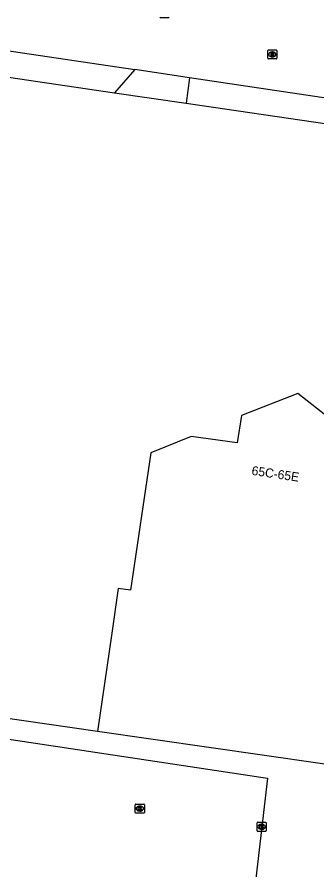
# Model space of a CAD drawing. Extents: x 163686 to 164493, y 382719 to 383870.
# Drawn here: x 163872 to 163905.1, y 382846.6 to 382940.9 of the extents above; entities that cross this region are included whole.
import ezdxf

# ---------------------------------------------------------------- set-up
doc = ezdxf.new("R2010")
doc.units = 0
for name, color, linetype in [('IMGEO_Groenvoorziening', 7, 'Continuous'), ('IMGEO_Hek', 7, 'Continuous'), ('IMGEO_Kolk', 7, 'Continuous'), ('IMGEO_Pand', 7, 'Continuous'), ('IMGEO_Pand_nummerreeks', 7, 'Continuous'), ('IMGEO_Parkeervlak_open', 7, 'Continuous'), ('IMGEO_Rijbaan_lokaal_gesloten', 7, 'Continuous'), ('IMGEO_Rioolput', 7, 'Continuous'), ('IMGEO_Voetpad_open', 7, 'Continuous')]:
    doc.layers.add(name, color=color, linetype=linetype)

msp = doc.modelspace()

# ---------------------------------------------------------------- linework, layer by layer
at = {"layer": 'IMGEO_Groenvoorziening'}
msp.add_lwpolyline([(163880.827, 382861.884), (163850.77, 382866.239), (163850.464, 382866.285)], dxfattribs=at)
at = {"layer": 'IMGEO_Hek'}
msp.add_lwpolyline([(163880.827, 382861.884), (163850.77, 382866.239), (163850.464, 382866.285)], dxfattribs=at)
at = {"layer": 'IMGEO_Kolk'}
for p, q in [((163888.672, 382940.839), (163887.82, 382940.839)), ((163885.017, 382852.936), (163885.017, 382853.788)), ((163885.092, 382853.862), (163885.944, 382853.862)), ((163885.505, 382853.642), (163885.53, 382853.642)), ((163886.018, 382853.788), (163886.018, 382852.936)), ((163885.944, 382852.862), (163885.092, 382852.862)), ((163885.528, 382853.082), (163885.503, 382853.082)), ((163898.468, 382850.916), (163898.468, 382851.768)), ((163898.543, 382851.842), (163899.395, 382851.842)), ((163898.956, 382851.622), (163898.981, 382851.622)), ((163899.469, 382851.768), (163899.469, 382850.916)), ((163899.395, 382850.842), (163898.543, 382850.842)), ((163898.979, 382851.062), (163898.954, 382851.062))]:
    msp.add_line(p, q, dxfattribs=at)
for points in [[(163888.672, 382940.839), (163887.82, 382940.839)], [(163885.017, 382852.936), (163885.017, 382853.788)], [(163885.092, 382853.862), (163885.944, 382853.862)], [(163885.338, 382853.562), (163885.461, 382853.562), (163885.461, 382853.411), (163885.591, 382853.562), (163885.755, 382853.562), (163885.609, 382853.411), (163885.762, 382853.162), (163885.61, 382853.162), (163885.525, 382853.326), (163885.461, 382853.259), (163885.461, 382853.162), (163885.338, 382853.162), (163885.338, 382853.562)], [(163886.018, 382853.788), (163886.018, 382852.936)], [(163885.944, 382852.862), (163885.092, 382852.862)], [(163898.468, 382850.916), (163898.468, 382851.768)], [(163898.543, 382851.842), (163899.395, 382851.842)], [(163898.789, 382851.542), (163898.912, 382851.542), (163898.912, 382851.391), (163899.042, 382851.542), (163899.206, 382851.542), (163899.06, 382851.391), (163899.213, 382851.142), (163899.061, 382851.142), (163898.976, 382851.306), (163898.912, 382851.239), (163898.912, 382851.142), (163898.789, 382851.142), (163898.789, 382851.542)], [(163899.469, 382851.768), (163899.469, 382850.916)], [(163899.395, 382850.842), (163898.543, 382850.842)]]:
    msp.add_lwpolyline(points, dxfattribs=at)
for centre, start, end in [((163887.822, 382940.915), 181.55205, 268.44795), ((163887.822, 382940.915), 181.55205, 268.44795), ((163888.67, 382940.915), 271.55205, 358.44795), ((163888.67, 382940.915), 271.55205, 358.44795), ((163885.094, 382853.786), 91.55205, 178.44795), ((163885.094, 382853.786), 91.55205, 178.44795), ((163885.942, 382853.786), 1.55205, 88.44795), ((163885.942, 382853.786), 1.55205, 88.44795), ((163885.094, 382852.938), 181.55205, 268.44795), ((163885.094, 382852.938), 181.55205, 268.44795), ((163885.942, 382852.938), 271.55205, 358.44795), ((163885.942, 382852.938), 271.55205, 358.44795), ((163898.545, 382851.766), 91.55205, 178.44795), ((163898.545, 382851.766), 91.55205, 178.44795), ((163899.393, 382851.766), 1.55205, 88.44795), ((163899.393, 382851.766), 1.55205, 88.44795), ((163898.545, 382850.918), 181.55205, 268.44795), ((163898.545, 382850.918), 181.55205, 268.44795), ((163899.393, 382850.918), 271.55205, 358.44795), ((163899.393, 382850.918), 271.55205, 358.44795)]:
    msp.add_arc(centre, 0.0765, start, end, dxfattribs=at)
for centre, major_axis, ratio, start_param, end_param in [((163885.504, 382853.362), (-0.387, 0.002), 0.722429, 4.712389, 7.853982), ((163885.529, 382853.362), (-0.39, 0.002), 0.717154, 1.570796, 4.712389), ((163898.955, 382851.342), (-0.387, 0.002), 0.722429, 4.712389, 7.853982), ((163898.98, 382851.342), (-0.39, 0.002), 0.717154, 1.570796, 4.712389)]:
    msp.add_ellipse(centre, major_axis=major_axis, ratio=ratio, start_param=start_param, end_param=end_param, dxfattribs=at)
at = {"layer": 'IMGEO_Pand'}
for points in [[(163920.248, 382872.441), (163914.398, 382873.277), (163916.567, 382888.528), (163912.866, 382891.394), (163907.711, 382892.144), (163908.123, 382895.2), (163902.973, 382899.267), (163896.743, 382896.84), (163896.27, 382893.82), (163891.181, 382894.499), (163886.72, 382892.723), (163884.497, 382877.503), (163883.129, 382877.692), (163882.409, 382872.745), (163880.827, 382861.884)], [(163917.731, 382856.565), (163880.827, 382861.884)]]:
    msp.add_lwpolyline(points, dxfattribs=at)
at = {"layer": 'IMGEO_Parkeervlak_open'}
for points in [[(163882.719, 382932.544), (163890.649, 382931.381)], [(163821.7, 382823.151), (163827.45, 382868.204), (163843.724, 382865.941), (163843.665, 382865.178), (163899.608, 382856.734), (163894.668, 382813.909)]]:
    msp.add_lwpolyline(points, dxfattribs=at)
at = {"layer": 'IMGEO_Rijbaan_lokaal_gesloten'}
for points in [[(163868.32, 382937.568), (163870.569, 382937.235), (163884.955, 382935.095)], [(163891.024, 382934.192), (163884.955, 382935.095)], [(163906.556, 382931.624), (163906.594, 382931.876), (163891.024, 382934.192)]]:
    msp.add_lwpolyline(points, dxfattribs=at)
at = {"layer": 'IMGEO_Rioolput'}
for p, q in [((163899.658, 382936.35), (163899.658, 382937.202)), ((163899.733, 382937.276), (163900.585, 382937.276)), ((163900.169, 382936.496), (163900.144, 382936.496)), ((163900.146, 382937.056), (163900.171, 382937.056)), ((163900.659, 382937.202), (163900.659, 382936.35)), ((163900.585, 382936.276), (163899.733, 382936.276))]:
    msp.add_line(p, q, dxfattribs=at)
for points in [[(163899.658, 382936.35), (163899.658, 382937.202)], [(163899.733, 382937.276), (163900.585, 382937.276)], [(163900.247, 382936.974), (163899.995, 382936.976), (163899.995, 382936.576)], [(163899.995, 382936.576), (163900.119, 382936.576), (163900.119, 382936.738), (163900.13, 382936.738)], [(163900.173, 382936.895), (163900.119, 382936.895), (163900.119, 382936.814)], [(163900.119, 382936.814), (163900.171, 382936.814)], [(163900.177, 382936.709), (163900.248, 382936.576), (163900.388, 382936.576), (163900.323, 382936.702)], [(163900.659, 382937.202), (163900.659, 382936.35)], [(163900.585, 382936.276), (163899.733, 382936.276)]]:
    msp.add_lwpolyline(points, dxfattribs=at)
for centre, radius, start, end in [((163899.735, 382937.2), 0.0765, 91.55205, 178.44795), ((163899.735, 382937.2), 0.0765, 91.55205, 178.44795), ((163900.129, 382936.685), 0.0533, 26.02933, 88.69889), ((163900.155, 382937.003), 0.19, 274.7715, 282.96867), ((163900.179, 382936.799), 0.0964, 77.00612, 93.18647), ((163900.193, 382936.856), 0.0378, 276.66336, 79.67722), ((163900.246, 382936.864), 0.109, 350.36119, 89.41601), ((163900.244, 382936.864), 0.112, 277.58423, 350.98172), ((163900.228, 382936.649), 0.108, 29.51342, 73.79051), ((163900.583, 382937.2), 0.0765, 1.55205, 88.44795), ((163900.583, 382937.2), 0.0765, 1.55205, 88.44795), ((163899.735, 382936.352), 0.0765, 181.55205, 268.44795), ((163899.735, 382936.352), 0.0765, 181.55205, 268.44795), ((163900.583, 382936.352), 0.0765, 271.55205, 358.44795), ((163900.583, 382936.352), 0.0765, 271.55205, 358.44795)]:
    msp.add_arc(centre, radius, start, end, dxfattribs=at)
for centre, major_axis, ratio, start_param, end_param in [((163900.145, 382936.776), (-0.387, 0.002), 0.722429, 4.712389, 7.853982), ((163900.17, 382936.776), (-0.39, 0.002), 0.717154, 1.570796, 4.712389)]:
    msp.add_ellipse(centre, major_axis=major_axis, ratio=ratio, start_param=start_param, end_param=end_param, dxfattribs=at)
at = {"layer": 'IMGEO_Voetpad_open'}
for points in [[(163884.955, 382935.095), (163882.719, 382932.544)], [(163870.994, 382934.264), (163882.719, 382932.544)], [(163891.024, 382934.192), (163890.649, 382931.381)], [(163890.649, 382931.381), (163906.226, 382929.097)]]:
    msp.add_lwpolyline(points, dxfattribs=at)

# ---------------------------------------------------------------- texts
at = {"layer": 'IMGEO_Pand_nummerreeks'}
msp.add_text('65C-65E', height=1, rotation=351.66598, dxfattribs=at).set_placement((163897.821, 382890.278))

doc.saveas('drawing.dxf')
